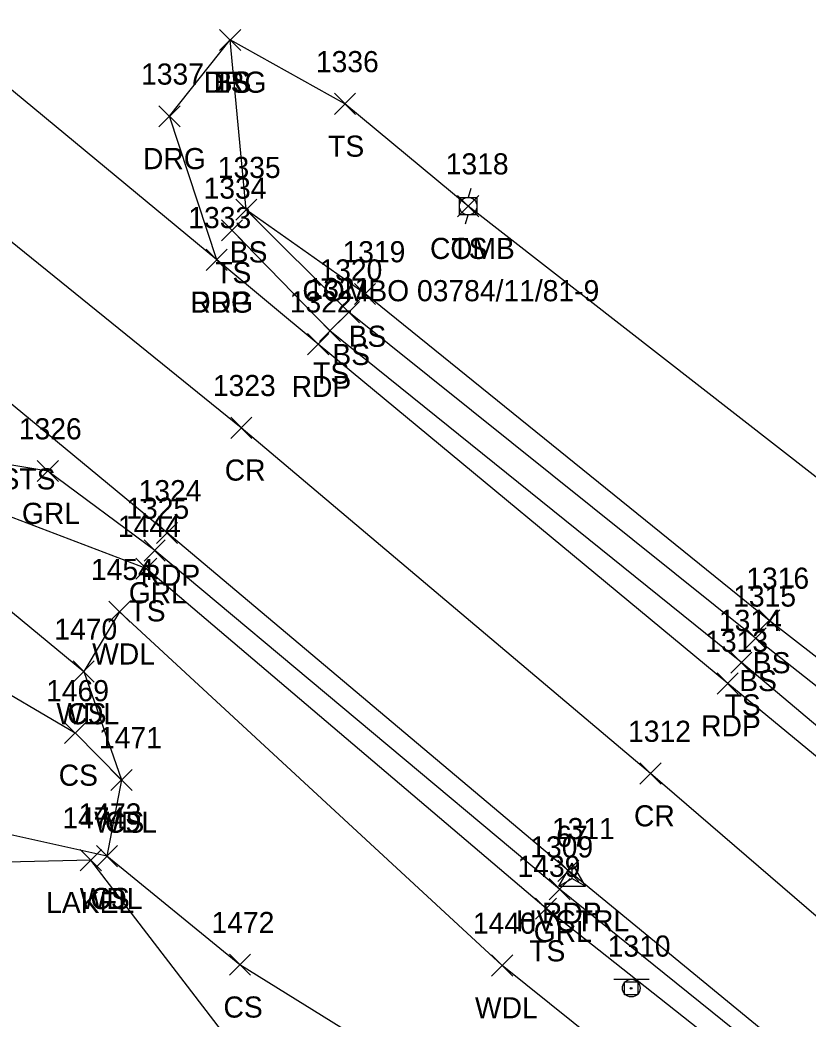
# Model space of a CAD drawing. Extents: x 1401404 to 1403982, y 557481 to 559873.
# Drawn here: x 1403062.3 to 1403136.9, y 558734 to 558828.6 of the extents above; entities that cross this region are included whole.
import ezdxf

# ---------------------------------------------------------------- set-up
doc = ezdxf.new("R2010")
doc.units = 0
for name, color, linetype in [('C_A', 7, 'Continuous'), ('C_I', 7, 'Continuous'), ('CPSM', 7, 'Continuous'), ('L_A', 7, 'Continuous'), ('L_I', 7, 'Continuous'), ('L_TIC', 7, 'Continuous'), ('LAWA', 7, 'Continuous'), ('LAWE', 7, 'Continuous'), ('LELB', 7, 'Continuous'), ('P_A', 7, 'Continuous'), ('P_I', 7, 'Continuous'), ('P_TIC', 7, 'Continuous'), ('PET', 7, 'Continuous'), ('PRC', 7, 'Continuous'), ('R_A', 7, 'Continuous'), ('R_C', 7, 'Continuous'), ('R_I', 7, 'Continuous'), ('R_TIC', 7, 'Continuous'), ('RDG', 7, 'Continuous'), ('RGR', 7, 'Continuous'), ('S_I', 7, 'Continuous'), ('SRM', 7, 'Continuous'), ('SSGN', 7, 'Continuous'), ('U_A', 7, 'Continuous'), ('U_C', 7, 'Continuous'), ('U_I', 7, 'Continuous'), ('UP', 7, 'Continuous')]:
    doc.layers.add(name, color=color, linetype=linetype)

msp = doc.modelspace()

# ---------------------------------------------------------------- linework, layer by layer
at = {"layer": 'CPSM'}
for p, q in [((1403113.282, 558746.612), (1403114.532, 558748.777)), ((1403115.782, 558746.612), (1403114.532, 558748.777)), ((1403114.532, 558747.333), (1403114.532, 558748.777)), ((1403113.282, 558746.612), (1403114.532, 558747.333)), ((1403114.532, 558747.333), (1403114.532, 558747.333)), ((1403114.532, 558747.333), (1403115.782, 558746.612)), ((1403113.282, 558746.612), (1403115.782, 558746.612))]:
    msp.add_line(p, q, dxfattribs=at)
at = {"layer": 'L_TIC'}
for points in [[(1403081.167, 558825.686), (1403083.167, 558827.686)], [(1403083.167, 558825.686), (1403081.167, 558827.686)], [(1403081.167, 558825.686), (1403083.167, 558827.686)], [(1403083.167, 558825.686), (1403081.167, 558827.686)], [(1403092.03, 558819.633), (1403094.03, 558821.633)], [(1403094.03, 558819.633), (1403092.03, 558821.633)], [(1403082.69, 558809.623), (1403084.69, 558811.623)], [(1403084.69, 558809.623), (1403082.69, 558811.623)], [(1403082.69, 558809.623), (1403084.69, 558811.623)], [(1403084.69, 558809.623), (1403082.69, 558811.623)], [(1403103.694, 558809.957), (1403105.694, 558811.957)], [(1403105.694, 558809.957), (1403103.694, 558811.957)], [(1403081.348, 558807.667), (1403083.348, 558809.667)], [(1403083.348, 558807.667), (1403081.348, 558809.667)], [(1403093.933, 558801.644), (1403095.933, 558803.644)], [(1403095.933, 558801.644), (1403093.933, 558803.644)], [(1403092.398, 558799.918), (1403094.398, 558801.918)], [(1403094.398, 558799.918), (1403092.398, 558801.918)], [(1403090.609, 558798.163), (1403092.609, 558800.163)], [(1403092.609, 558798.163), (1403090.609, 558800.163)], [(1403073.233, 558775.659), (1403075.233, 558777.659)], [(1403075.233, 558775.659), (1403073.233, 558777.659)], [(1403070.692, 558771.58), (1403072.692, 558773.58)], [(1403072.692, 558771.58), (1403070.692, 558773.58)], [(1403132.188, 558770.754), (1403134.188, 558772.754)], [(1403134.188, 558770.754), (1403132.188, 558772.754)], [(1403130.897, 558769.061), (1403132.897, 558771.061)], [(1403132.897, 558769.061), (1403130.897, 558771.061)], [(1403129.546, 558766.757), (1403131.546, 558768.757)], [(1403131.546, 558766.757), (1403129.546, 558768.757)], [(1403067.31, 558765.926), (1403069.31, 558767.926)], [(1403069.31, 558765.926), (1403067.31, 558767.926)], [(1403067.31, 558765.926), (1403069.31, 558767.926)], [(1403069.31, 558765.926), (1403067.31, 558767.926)], [(1403066.502, 558760.109), (1403068.502, 558762.109)], [(1403068.502, 558760.109), (1403066.502, 558762.109)], [(1403070.884, 558755.662), (1403072.884, 558757.662)], [(1403072.884, 558755.662), (1403070.884, 558757.662)], [(1403070.884, 558755.662), (1403072.884, 558757.662)], [(1403072.884, 558755.662), (1403070.884, 558757.662)], [(1403067.989, 558748.068), (1403069.989, 558750.068)], [(1403069.989, 558748.068), (1403067.989, 558750.068)], [(1403069.512, 558748.441), (1403071.512, 558750.441)], [(1403071.512, 558748.441), (1403069.512, 558750.441)], [(1403069.512, 558748.441), (1403071.512, 558750.441)], [(1403071.512, 558748.441), (1403069.512, 558750.441)], [(1403111.062, 558743.487), (1403113.062, 558745.487)], [(1403113.062, 558743.487), (1403111.062, 558745.487)], [(1403082.095, 558738.17), (1403084.095, 558740.17)], [(1403084.095, 558738.17), (1403082.095, 558740.17)], [(1403106.914, 558738.102), (1403108.914, 558740.102)], [(1403108.914, 558738.102), (1403106.914, 558740.102)]]:
    msp.add_lwpolyline(points, dxfattribs=at)
at = {"layer": 'LAWA'}
msp.add_lwpolyline([(1403316.657, 558597.36), (1403281.729, 558613.911), (1403272.537, 558615.21), (1403248.231, 558629.227), (1403213.478, 558654.181), (1403180.64, 558681.313), (1403143.75, 558710.337), (1403107.914, 558739.102), (1403071.692, 558772.58), (1403068.31, 558766.926), (1403071.884, 558756.662), (1403070.512, 558749.441)], dxfattribs=at)
at = {"layer": 'LAWE'}
msp.add_lwpolyline([(1403238.681, 558611.558), (1403231.812, 558615.037), (1403202.572, 558639.469), (1403173.172, 558667.726), (1403127.979, 558695.57), (1403090.177, 558721.426), (1403068.989, 558749.068), (1403055.639, 558748.741), (1403047.531, 558763.161), (1403042.819, 558768.94)], dxfattribs=at)
at = {"layer": 'LELB'}
for points in [[(1403267.846, 558683.335), (1403245.233, 558701.537), (1403233.301, 558710.317), (1403211.5, 558722.873), (1403177.528, 558752.488), (1403141.193, 558782.55), (1403104.694, 558810.957), (1403093.03, 558820.633), (1403082.167, 558826.686)], [(1403274.012, 558661.519), (1403275.402, 558663.642), (1403262.104, 558673.196), (1403240.708, 558692.984), (1403238.023, 558696.32), (1403228.06, 558701.884), (1403206.411, 558715.04), (1403170.23, 558742.972), (1403133.188, 558771.754), (1403094.933, 558802.644), (1403083.69, 558810.623), (1403082.167, 558826.686)], [(1403274.012, 558661.519), (1403260.473, 558670.14), (1403237.928, 558689.804), (1403236.558, 558692.649), (1403235.186, 558693.985), (1403226.373, 558700.515), (1403205.438, 558713.368), (1403168.701, 558741.028), (1403131.897, 558770.061), (1403093.398, 558800.918), (1403083.69, 558810.623)], [(1403274.012, 558661.519), (1403259.107, 558668.052), (1403235.315, 558685.624), (1403232.732, 558691.668), (1403222.735, 558697.605), (1403203.011, 558709.686), (1403165.843, 558738.032), (1403130.546, 558767.757), (1403091.609, 558799.163), (1403082.348, 558808.667)], [(1403036.52, 558802.994), (1403040.675, 558792.723), (1403045.494, 558785.776), (1403068.31, 558766.926)], [(1403567.19, 558568.672), (1403521.327, 558570.05), (1403484.768, 558571.485), (1403436.828, 558574.711), (1403390.353, 558579.879), (1403360.169, 558585.19), (1403345.928, 558587.285), (1403333.514, 558592.26), (1403317.515, 558600.618), (1403299.002, 558608.828), (1403282.939, 558617.965), (1403248.094, 558638.933), (1403217.119, 558660.936), (1403185.325, 558684.7), (1403148.792, 558715.456), (1403112.062, 558744.487), (1403074.233, 558776.659), (1403055.653, 558783.747), (1403043.183, 558796.215), (1403041.062, 558801.071)], [(1403035.333, 558791.822), (1403038.373, 558786.596), (1403045.88, 558778.163), (1403050.376, 558774.251), (1403058.051, 558766.679), (1403067.502, 558761.109), (1403071.884, 558756.662)], [(1403083.095, 558739.17), (1403070.512, 558749.441), (1403059.101, 558751.979), (1403048.949, 558763.532), (1403043.664, 558769.94), (1403037.589, 558779.198)], [(1403100.625, 558728.291), (1403083.095, 558739.17)]]:
    msp.add_lwpolyline(points, dxfattribs=at)
at = {"layer": 'P_TIC'}
for points in [[(1403079.901, 558804.872), (1403081.901, 558806.872)], [(1403081.901, 558804.872), (1403079.901, 558806.872)], [(1403089.497, 558796.896), (1403091.497, 558798.896)], [(1403091.497, 558796.896), (1403089.497, 558798.896)], [(1403082.224, 558788.984), (1403084.224, 558790.984)], [(1403084.224, 558788.984), (1403082.224, 558790.984)], [(1403075.198, 558779.032), (1403077.198, 558781.032)], [(1403077.198, 558779.032), (1403075.198, 558781.032)], [(1403128.248, 558764.781), (1403130.248, 558766.781)], [(1403130.248, 558764.781), (1403128.248, 558766.781)], [(1403120.948, 558756.263), (1403122.948, 558758.263)], [(1403122.948, 558756.263), (1403120.948, 558758.263)], [(1403113.176, 558747.056), (1403115.176, 558749.056)], [(1403115.176, 558747.056), (1403113.176, 558749.056)]]:
    msp.add_lwpolyline(points, dxfattribs=at)
at = {"layer": 'PET'}
for points in [[(1403164.555, 558736.666), (1403129.248, 558765.781), (1403090.497, 558797.896), (1403080.901, 558805.872), (1403055.947, 558826.49), (1403037.693, 558840.863), (1403021.818, 558852), (1403010.766, 558860.563), (1402965.567, 558891.006), (1402927.929, 558913.53), (1402884.611, 558936.362), (1402848.098, 558956.632), (1402812.557, 558974.835), (1402775.42, 558993.623)], [(1403567.323, 558571.161), (1403521.055, 558571.892), (1403485.08, 558573.953), (1403437.345, 558577.288), (1403390.926, 558583.548), (1403361.613, 558591.03), (1403321.823, 558602.545), (1403283.736, 558620.332), (1403244.193, 558645.3), (1403219.218, 558663.606), (1403205.442, 558672.119), (1403186.056, 558688.409), (1403150.644, 558718.107), (1403114.176, 558748.056), (1403076.198, 558780.032), (1403043.936, 558806.704), (1402997.13, 558841.767), (1402954.247, 558870.687), (1402915.87, 558893.532), (1402876.179, 558915.415), (1402801.328, 558955.205), (1402766.491, 558972.95)]]:
    msp.add_lwpolyline(points, dxfattribs=at)
at = {"layer": 'PRC'}
msp.add_lwpolyline([(1403567.874, 558582.773), (1403521.719, 558584.551), (1403486.229, 558585.007), (1403438.972, 558588.433), (1403393.102, 558594.896), (1403360.826, 558602.705), (1403288.915, 558631.603), (1403250.295, 558655.214), (1403225.89, 558672.347), (1403193.368, 558698.042), (1403157.152, 558726.964), (1403121.948, 558757.263), (1403083.224, 558789.984), (1403051.101, 558815.937), (1403004.274, 558851.49), (1402960.213, 558880.82), (1402921.635, 558903.817), (1402881.318, 558926.058), (1402807.323, 558964.726), (1402770.827, 558983.445)], dxfattribs=at)
at = {"layer": 'R_TIC'}
for points in [[(1403081.167, 558825.686), (1403083.167, 558827.686)], [(1403083.167, 558825.686), (1403081.167, 558827.686)], [(1403075.43, 558818.456), (1403077.43, 558820.456)], [(1403077.43, 558818.456), (1403075.43, 558820.456)], [(1403079.901, 558804.872), (1403081.901, 558806.872)], [(1403081.901, 558804.872), (1403079.901, 558806.872)], [(1403063.917, 558784.886), (1403065.917, 558786.886)], [(1403065.917, 558784.886), (1403063.917, 558786.886)], [(1403074.032, 558777.374), (1403076.032, 558779.374)], [(1403076.032, 558777.374), (1403074.032, 558779.374)], [(1403112.349, 558745.324), (1403114.349, 558747.324)], [(1403114.349, 558745.324), (1403112.349, 558747.324)]]:
    msp.add_lwpolyline(points, dxfattribs=at)
at = {"layer": 'RDG'}
msp.add_lwpolyline([(1403080.901, 558805.872), (1403076.43, 558819.456), (1403082.167, 558826.686)], dxfattribs=at)
at = {"layer": 'RGR'}
msp.add_lwpolyline([(1403343.042, 558588.832), (1403321.634, 558601.07), (1403283.23, 558619.584), (1403243.098, 558643.516), (1403218.12, 558661.744), (1403185.478, 558687.648), (1403149.871, 558716.896), (1403113.349, 558746.324), (1403075.032, 558778.374), (1403064.917, 558785.886), (1403057.128, 558787.174)], dxfattribs=at)
at = {"layer": 'SRM'}
msp.add_lwpolyline([(1403119.481, 558737.564), (1403120.731, 558737.564), (1403120.731, 558736.314), (1403119.481, 558736.314)], close=True, dxfattribs=at)
msp.add_circle((1403120.106, 558736.939), 0.0833, dxfattribs=at)
at = {"layer": 'SSGN'}
for p, q in [((1403118.479, 558737.793), (1403121.812, 558737.793)), ((1403120.126, 558736.959), (1403120.126, 558736.959))]:
    msp.add_line(p, q, dxfattribs=at)
msp.add_circle((1403120.126, 558736.959), 0.833, dxfattribs=at)
at = {"layer": 'UP'}
for p, q in [((1403104.944, 558812.623), (1403104.694, 558811.79)), ((1403103.86, 558810.123), (1403103.86, 558811.79)), ((1403103.86, 558811.79), (1403105.527, 558811.79)), ((1403105.527, 558811.79), (1403105.527, 558810.123)), ((1403104.694, 558810.957), (1403104.694, 558810.957)), ((1403105.527, 558810.123), (1403103.86, 558810.123)), ((1403104.444, 558809.29), (1403104.694, 558810.123))]:
    msp.add_line(p, q, dxfattribs=at)
msp.add_circle((1403104.694, 558810.957), 0.833, dxfattribs=at)

# ---------------------------------------------------------------- texts
at = {"layer": 'C_A'}
msp.add_text('HVCTRL', height=2, dxfattribs=at).set_placement((1403109.225, 558742.333))
at = {"layer": 'C_I'}
msp.add_text('67', height=2, dxfattribs=at).set_placement((1403113.02, 558750.333))
at = {"layer": 'L_A'}
for s, p in [('TS', (1403080.577, 558821.686)), ('BS', (1403080.608, 558821.686)), ('TS', (1403091.439, 558815.633)), ('BS', (1403082.131, 558805.623)), ('BS', (1403082.131, 558805.623)), ('TS', (1403103.103, 558805.957)), ('TS', (1403080.757, 558803.667)), ('BS', (1403093.374, 558797.644)), ('BS', (1403091.839, 558795.918)), ('TS', (1403090.019, 558794.163)), ('TS', (1403072.642, 558771.659)), ('WDL', (1403069.109, 558767.58)), ('BS', (1403131.629, 558766.754)), ('BS', (1403130.338, 558765.061)), ('TS', (1403128.956, 558762.757)), ('WDL', (1403065.727, 558761.926)), ('CS', (1403066.751, 558761.926)), ('CS', (1403065.943, 558756.109)), ('WDL', (1403069.301, 558751.662)), ('CS', (1403070.325, 558751.662)), ('LAKEL', (1403064.753, 558744.068)), ('WDL', (1403067.93, 558744.441)), ('CS', (1403068.953, 558744.441)), ('TS', (1403110.472, 558739.487)), ('CS', (1403081.536, 558734.17)), ('WDL', (1403105.332, 558734.102))]:
    msp.add_text(s, height=2, dxfattribs=at).set_placement(p)
at = {"layer": 'L_I'}
for s, p in [('1336', (1403090.282, 558823.633)), ('1335', (1403080.997, 558813.623)), ('1335', (1403080.997, 558813.623)), ('1318', (1403102.568, 558813.957)), ('1334', (1403079.655, 558811.667)), ('1319', (1403092.799, 558805.644)), ('1320', (1403090.618, 558803.918)), ('1321', (1403089.483, 558802.163)), ('1444', (1403071.54, 558779.659)), ('1454', (1403068.999, 558775.58)), ('1316', (1403131.007, 558774.754)), ('1315', (1403129.771, 558773.061)), ('1314', (1403128.42, 558770.757)), ('1470', (1403065.53, 558769.926)), ('1470', (1403065.53, 558769.926)), ('1469', (1403064.754, 558764.109)), ('1471', (1403069.758, 558759.662)), ('1471', (1403069.758, 558759.662)), ('1474', (1403066.296, 558752.068)), ('1473', (1403067.819, 558752.441)), ('1473', (1403067.819, 558752.441)), ('1439', (1403109.362, 558747.487)), ('1472', (1403080.402, 558742.17)), ('1440', (1403105.135, 558742.102))]:
    msp.add_text(s, height=2, dxfattribs=at).set_placement(p)
at = {"layer": 'P_A'}
for s, p in [('RDP', (1403078.389, 558800.872)), ('RDP', (1403087.985, 558792.896)), ('CR', (1403081.657, 558784.984)), ('RDP', (1403073.686, 558775.032)), ('RDP', (1403126.736, 558760.781)), ('CR', (1403120.381, 558752.263)), ('RDP', (1403111.664, 558743.056))]:
    msp.add_text(s, height=2, dxfattribs=at).set_placement(p)
at = {"layer": 'P_I'}
for s, p in [('1333', (1403078.208, 558808.872)), ('1322', (1403087.804, 558800.896)), ('1323', (1403080.531, 558792.984)), ('1324', (1403073.505, 558783.032)), ('1313', (1403127.122, 558768.781)), ('1312', (1403119.822, 558760.263)), ('1311', (1403112.617, 558751.056))]:
    msp.add_text(s, height=2, dxfattribs=at).set_placement(p)
at = {"layer": 'R_A'}
for s, p in [('DRG', (1403079.656, 558821.686)), ('DRG', (1403073.918, 558814.456)), ('DRG', (1403078.389, 558800.872)), ('GRL', (1403062.461, 558780.886)), ('GRL', (1403072.575, 558773.374)), ('GRL', (1403110.892, 558741.324))]:
    msp.add_text(s, height=2, dxfattribs=at).set_placement(p)
at = {"layer": 'R_C'}
msp.add_text('STR WITH STFFL POSTS', height=2, dxfattribs=at).set_placement((1403033.994, 558784.152))
at = {"layer": 'R_I'}
for s, p in [('1337', (1403073.737, 558822.456)), ('1333', (1403078.208, 558808.872)), ('1326', (1403062.169, 558788.886)), ('1325', (1403072.339, 558781.374)), ('1309', (1403110.569, 558749.324))]:
    msp.add_text(s, height=2, dxfattribs=at).set_placement(p)
at = {"layer": 'S_I'}
msp.add_text('1310', height=2, dxfattribs=at).set_placement((1403117.894, 558739.939))
msp.add_text('1310', height=2, dxfattribs=at).set_placement((1403117.894, 558739.939))
at = {"layer": 'U_A'}
msp.add_text('COMB', height=2, dxfattribs=at).set_placement((1403101.079, 558805.957))
at = {"layer": 'U_C'}
msp.add_text('COMBO 03784/11/81-9', height=2, dxfattribs=at).set_placement((1403089.001, 558801.957))
at = {"layer": 'U_I'}
msp.add_text('1318', height=2, dxfattribs=at).set_placement((1403102.568, 558813.957))

doc.saveas('drawing.dxf')
